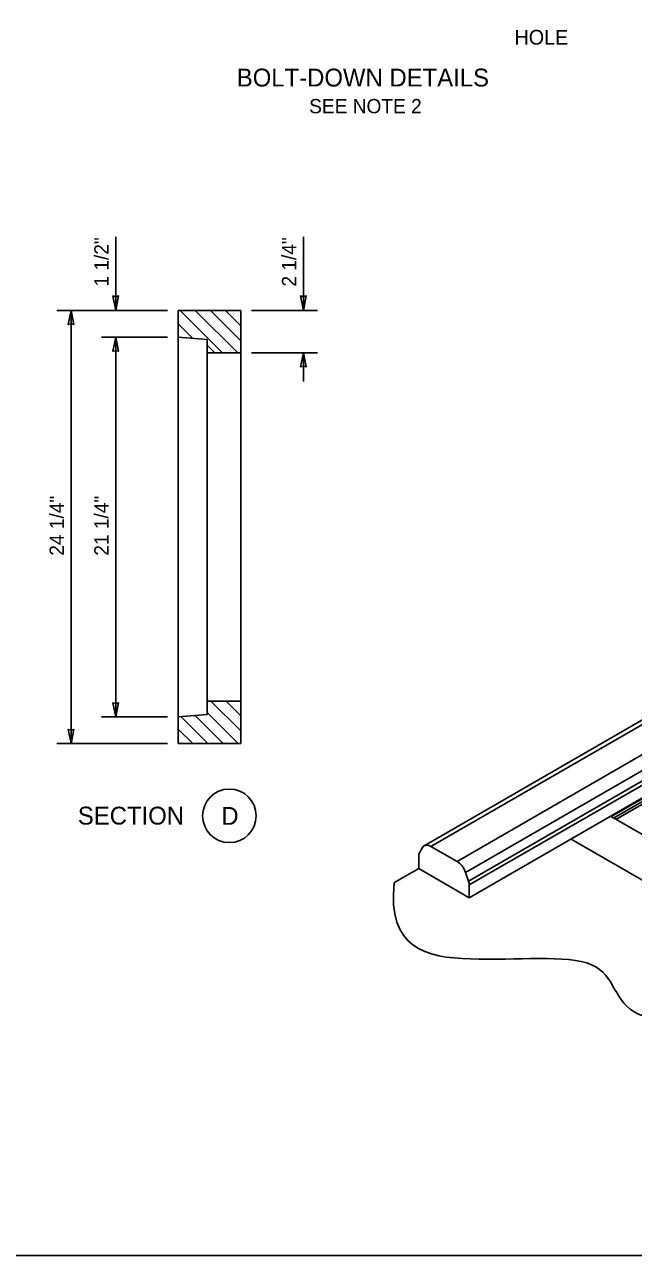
# Model space of a CAD drawing. Extents: x 99862 to 103151, y 100000 to 102076.
# Drawn here: x 101128 to 101809, y 100000 to 101378 of the extents above; entities that cross this region are included whole.
import ezdxf

# ---------------------------------------------------------------- set-up
doc = ezdxf.new("R2010")
doc.units = 0
for name, color, linetype in [('Default', 7, 'Continuous'), ('Level 1', 7, 'Continuous'), ('Level 14', 7, 'Continuous'), ('Level 15', 7, 'Continuous'), ('Level 17', 7, 'Continuous'), ('Level 19', 7, 'Continuous'), ('Level 2', 7, 'Continuous'), ('Level 20', 7, 'Continuous'), ('Level 27', 7, 'Continuous'), ('Level 4', 7, 'Continuous'), ('Level 5', 7, 'Continuous'), ('Level 62', 7, 'Continuous'), ('Level 7', 7, 'Continuous'), ('Level 8', 7, 'Continuous')]:
    doc.layers.add(name, color=color, linetype=linetype)

msp = doc.modelspace()

# ---------------------------------------------------------------- linework, layer by layer
at = {"layer": 'Default'}
for points in [[(101230, 101057.7), (101233.2, 101074), (101230, 101073.2), (101226.8, 101074)], [(101440, 101057.7), (101443.2, 101074), (101440, 101073.2), (101436.8, 101074)]]:
    msp.add_lwpolyline(points, close=True, dxfattribs=at)
at = {"layer": 'Level 1'}
for p, q in [((101300, 100602.7), (101300, 101027.7)), ((101332.5, 100620.2), (101332.5, 101010.2)), ((101370, 101010.2), (101370, 100620.2))]:
    msp.add_line(p, q, dxfattribs=at)
msp.add_lwpolyline([(99862, 99999.5), (103151, 99999.5), (103151, 102075.5), (99862, 102075.5)], close=True, dxfattribs=at)
at = {"layer": 'Level 14'}
for p, q in [((101230, 101057.7), (101230, 101140.3)), ((101440, 101057.7), (101440, 101140.3))]:
    msp.add_line(p, q, dxfattribs=at)
at = {"layer": 'Level 15'}
for p, q in [((101164, 101057.7), (101288, 101057.7)), ((101180, 100572.7), (101180, 101057.7)), ((101456, 101057.7), (101382, 101057.7)), ((101214, 101027.7), (101288, 101027.7)), ((101230, 100602.7), (101230, 101027.7)), ((101456, 101010.2), (101382, 101010.2)), ((101440, 100978.2), (101440, 101010.2)), ((101214, 100602.7), (101288, 100602.7)), ((101164, 100572.7), (101288, 100572.7))]:
    msp.add_line(p, q, dxfattribs=at)
for points in [[(101180, 101057.7), (101176.9, 101042), (101180, 101042.7), (101183.1, 101042)], [(101230, 101027.7), (101226.9, 101012), (101230, 101012.7), (101233.1, 101012)], [(101440, 101010.2), (101443.1, 100994.5), (101440, 100995.2), (101436.9, 100994.5)], [(101230, 100602.7), (101226.9, 100618.5), (101230, 100617.7), (101233.1, 100618.5)], [(101180, 100572.7), (101176.9, 100588.5), (101180, 100587.7), (101183.1, 100588.5)]]:
    msp.add_lwpolyline(points, close=True, dxfattribs=at)
at = {"layer": 'Level 17'}
for p, q in [((101302, 101057.7), (101349.5, 101010.2)), ((101319, 101057.7), (101366.5, 101010.2)), ((101336, 101057.7), (101370, 101023.7)), ((101352.9, 101057.7), (101370, 101040.7)), ((101369.9, 101057.7), (101370, 101057.6)), ((101300, 101042.8), (101316.3, 101026.5)), ((101332.5, 101018.8), (101341, 101010.2)), ((101332.5, 101010.3), (101332.5, 101010.2)), ((101336.6, 100620.2), (101370, 100586.9)), ((101353.6, 100620.2), (101370, 100603.8)), ((101303, 100603), (101333.2, 100572.7)), ((101318.8, 100604.2), (101350.2, 100572.7)), ((101332.5, 100607.4), (101367.2, 100572.7)), ((101300, 100589), (101316.3, 100572.7))]:
    msp.add_line(p, q, dxfattribs=at)
at = {"layer": 'Level 2'}
msp.add_line((101961.4, 100586.8), (101789.9, 100487.8), dxfattribs=at)
for points in [[(101370, 101057.7), (101300, 101057.7)], [(101300, 101057.7), (101300, 101027.7)], [(101370, 101010.2), (101370, 101057.7)], [(101300, 101027.7), (101332.5, 101025.2)], [(101332.5, 101025.2), (101332.5, 101010.2)], [(101332.5, 101010.2), (101370, 101010.2)], [(101332.5, 100620.2), (101370, 100620.2)], [(101332.5, 100605.2), (101332.5, 100620.2)], [(101370, 100620.2), (101370, 100572.7)], [(101300, 100602.7), (101332.5, 100605.2)], [(101300, 100572.7), (101300, 100602.7)], [(101370, 100572.7), (101300, 100572.7)]]:
    msp.add_lwpolyline(points, dxfattribs=at)
at = {"layer": 'Level 27'}
for p, q in [((102072.1, 100740.1), (101582.7, 100457.6)), ((102101.4, 100723.2), (101612.1, 100440.6)), ((102110.9, 100710.9), (101621.5, 100428.4)), ((102114.3, 100701.1), (101624.9, 100418.6)), ((102115.1, 100697), (101625.7, 100414.5))]:
    msp.add_line(p, q, dxfattribs=at)
at = {"layer": 'Level 4'}
for p, q in [((101957.9, 100590.9), (101784.6, 100490.9)), ((101787.3, 100489.3), (101960.5, 100589.3)), ((102124, 100294.9), (101784.6, 100490.9))]:
    msp.add_line(p, q, dxfattribs=at)
msp.add_lwpolyline([(101784.6, 100490.9), (101784.6, 100490.9), (101787.3, 100489.3)], dxfattribs=at)
at = {"layer": 'Level 5'}
for points, degree in [([(101541.6, 100416.9), (101533.9, 100343.4), (101619.7, 100322.8), (101793.3, 100343.8), (101783.3, 100252.1), (101964.9, 100265.8), (102040.9, 100180.2), (102164.1, 100269.6), (102309, 100272.6), (102352, 100371.7), (102500.8, 100417.1), (102339.7, 100457.8), (102377.9, 100546.6), (102178.5, 100580.3), (102177.2, 100643.6), (102170.7, 100711.9), (102127.4, 100738.7), (102102.4, 100740.7)], 3), ([(101569.1, 100432.8), (101559.9, 100427.5), (101550.8, 100422.2), (101541.6, 100416.9)], 2)]:
    msp.add_open_spline(points, degree=degree, dxfattribs=at)
at = {"layer": 'Level 7'}
for p, q in [((102064.6, 100740.8), (101575.2, 100458.3)), ((102115.1, 100682.6), (101625.7, 100400.1)), ((101582.7, 100457.6), (101612.1, 100440.6)), ((102101.1, 100257.1), (101739.6, 100465.8)), ((101569.1, 100432.8), (101569.1, 100447.2)), ((101569.9, 100450.4), (101573.3, 100456.3)), ((101625.7, 100400.1), (101569.1, 100432.8)), ((101621.5, 100428.4), (101624.9, 100418.6)), ((101625.7, 100414.5), (101625.7, 100400.1))]:
    msp.add_line(p, q, dxfattribs=at)
for centre, major_axis, start_param, end_param in [((101582.7, 100445.3), (7.5, -13), 2.356194, 3.463343), ((101576.2, 100443.1), (5, -8.66), 3.463343, 3.926991), ((101612.1, 100428.4), (7.5, -13), 1.249046, 2.356194), ((101618.6, 100418.6), (5, -8.66), 0.785398, 1.249046)]:
    msp.add_ellipse(centre, major_axis=major_axis, ratio=0.57735, start_param=start_param, end_param=end_param, dxfattribs=at)
at = {"layer": 'Level 8'}
msp.add_circle((101357.2, 100491.8), 30, dxfattribs=at)

# ---------------------------------------------------------------- texts
at = {"layer": 'Level 1'}
msp.add_text('HOLE', height=16.5, dxfattribs=at).set_placement((101676.4, 101355.5))
at = {"layer": 'Level 19'}
msp.add_text('SECTION', height=20, dxfattribs=at).set_placement((101187.6, 100482))
at = {"layer": 'Level 20'}
for s, p in [('BOLT-DOWN DETAILS', (101365.5, 101308.6)), ('D', (101348.2, 100481.7))]:
    msp.add_text(s, height=20, dxfattribs=at).set_placement(p)
for s, p in [('1 1/2"', (101222, 101084.5)), ('2 1/4"', (101432, 101084.5)), ('24 1/4"', (101172, 100783.1)), ('21 1/4"', (101222, 100783.1))]:
    msp.add_text(s, height=16, rotation=90, dxfattribs=at).set_placement(p)
at = {"layer": 'Level 62'}
msp.add_text('SEE NOTE 2', height=16, dxfattribs=at).set_placement((101446.5, 101278.6))

doc.saveas('drawing.dxf')
